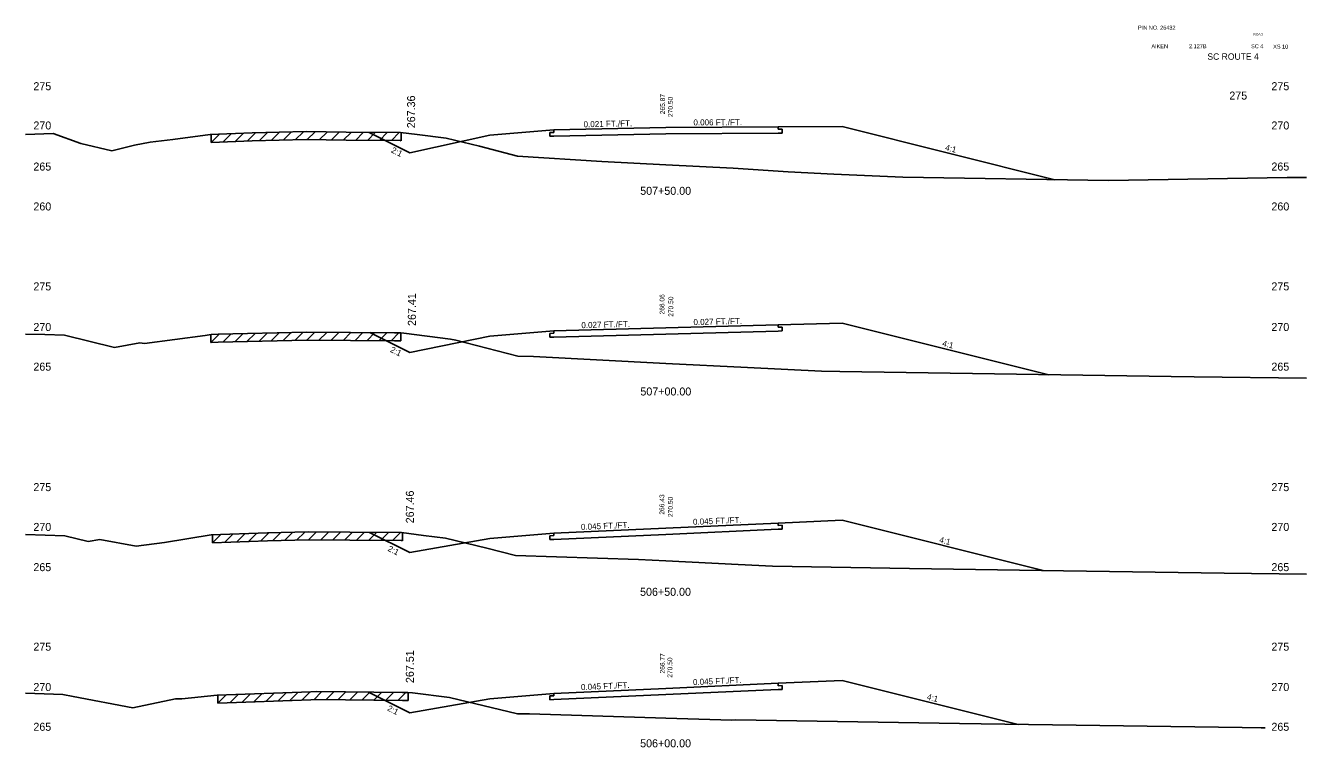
# Model space of a CAD drawing. Extents: x 883 to 1160, y 1002 to 4323.
# Drawn here: x 1000 to 1160, y 2048.1 to 2138.2 of the extents above; entities that cross this region are included whole.
import ezdxf

# ---------------------------------------------------------------- set-up
doc = ezdxf.new("R2010")
doc.units = 0
for name, color, linetype in [('Level 1', 7, 'Continuous'), ('Level 10', 7, 'Continuous'), ('Level 11', 7, 'Continuous'), ('Level 12', 7, 'Continuous'), ('Level 3', 7, 'Continuous'), ('Level 32', 7, 'Continuous'), ('Level 33', 7, 'Continuous'), ('Level 59', 7, 'Continuous'), ('Level 6', 7, 'Continuous'), ('Level 60', 7, 'Continuous'), ('Level 61', 7, 'Continuous'), ('Level 7', 7, 'Continuous')]:
    doc.layers.add(name, color=color, linetype=linetype)

msp = doc.modelspace()

# ---------------------------------------------------------------- linework, layer by layer
at = {"layer": 'Level 11'}
for p, q in [((1066, 2124.91), (1065.5, 2124.9)), ((1065.5, 2124.9), (1065.5, 2124.42)), ((1066, 2125.21), (1066, 2124.91)), ((1094, 2125.29), (1094, 2125.59)), ((1094.5, 2125.29), (1094, 2125.29)), ((1094, 2124.81), (1094.5, 2124.81)), ((1094.5, 2124.81), (1094.5, 2125.29)), ((1065.5, 2124.42), (1066, 2124.43)), ((1094, 2100.58), (1094, 2100.88)), ((1066, 2099.82), (1065.5, 2099.8)), ((1065.5, 2099.8), (1065.5, 2099.32)), ((1065.5, 2099.32), (1066, 2099.34)), ((1066, 2100.12), (1066, 2099.82)), ((1094.5, 2100.6), (1094, 2100.58)), ((1094, 2100.1), (1094.5, 2100.12)), ((1094.5, 2100.12), (1094.5, 2100.6)), ((1094, 2075.83), (1094, 2076.13)), ((1094.5, 2075.85), (1094, 2075.83)), ((1094, 2075.35), (1094.5, 2075.37)), ((1094.5, 2075.37), (1094.5, 2075.85)), ((1066, 2074.57), (1065.5, 2074.55)), ((1065.5, 2074.55), (1065.5, 2074.07)), ((1065.5, 2074.07), (1066, 2074.09)), ((1066, 2074.87), (1066, 2074.57)), ((1094, 2055.83), (1094, 2056.13)), ((1066, 2054.57), (1065.5, 2054.55)), ((1065.5, 2054.55), (1065.5, 2054.07)), ((1066, 2054.87), (1066, 2054.57)), ((1094.5, 2055.85), (1094, 2055.83)), ((1094, 2055.35), (1094.5, 2055.37)), ((1094.5, 2055.37), (1094.5, 2055.85)), ((1065.5, 2054.07), (1066, 2054.09))]:
    msp.add_line(p, q, dxfattribs=at)
at = {"layer": 'Level 12'}
for p, q in [((1094, 2124.81), (1080, 2124.72)), ((1080, 2124.72), (1066, 2124.43)), ((1080, 2099.72), (1066, 2099.34)), ((1094, 2100.1), (1080, 2099.72)), ((1094, 2075.35), (1080, 2074.72)), ((1080, 2074.72), (1066, 2074.09)), ((1080, 2054.72), (1066, 2054.09)), ((1094, 2055.35), (1080, 2054.72))]:
    msp.add_line(p, q, dxfattribs=at)
at = {"layer": 'Level 59'}
for p, q in [((1066, 2125.21), (1080, 2125.5)), ((1080, 2125.5), (1094, 2125.59)), ((1080, 2100.5), (1094, 2100.88)), ((1066, 2100.12), (1080, 2100.5)), ((1066, 2074.87), (1080, 2075.5)), ((1080, 2075.5), (1094, 2076.13)), ((1080, 2055.5), (1094, 2056.13)), ((1066, 2054.87), (1080, 2055.5))]:
    msp.add_line(p, q, dxfattribs=at)
at = {"layer": 'Level 6'}
for p, q in [((1058, 2124.54), (1066, 2125.21)), ((1094, 2125.59), (1102, 2125.64)), ((1094, 2100.88), (1102, 2101.1)), ((1058, 2099.45), (1066, 2100.12)), ((1094, 2076.13), (1102, 2076.49)), ((1058, 2074.2), (1066, 2074.87)), ((1094, 2056.13), (1102, 2056.49)), ((1058, 2054.2), (1066, 2054.87))]:
    msp.add_line(p, q, dxfattribs=at)
at = {"layer": 'Level 60'}
for p, q in [((1023.07, 2124.65), (1028.29, 2124.84)), ((1028.29, 2124.84), (1035.06, 2125)), ((1035.06, 2125), (1040.06, 2124.92)), ((1040.06, 2124.92), (1046.83, 2124.88)), ((1046.83, 2124.88), (1048.93, 2124.64)), ((1000, 2124.63), (1003.46, 2124.77)), ((1003.46, 2124.77), (1006.89, 2123.53)), ((1006.89, 2123.53), (1010.75, 2122.61)), ((1010.75, 2122.61), (1013.62, 2123.33)), ((1013.62, 2123.33), (1015.56, 2123.69)), ((1015.56, 2123.69), (1018.39, 2124.03)), ((1018.39, 2124.03), (1023.07, 2124.65)), ((1048.93, 2124.64), (1052.52, 2124.18)), ((1052.52, 2124.18), (1056.7, 2123.17)), ((1056.7, 2123.17), (1061.46, 2121.95)), ((1061.46, 2121.95), (1071.98, 2121.28)), ((1071.98, 2121.28), (1080, 2120.87)), ((1080, 2120.87), (1088.39, 2120.44)), ((1088.39, 2120.44), (1095.27, 2119.97)), ((1095.27, 2119.97), (1100.97, 2119.68)), ((1100.97, 2119.68), (1109.58, 2119.3)), ((1109.58, 2119.3), (1135.28, 2118.9)), ((1135.28, 2118.9), (1157.59, 2119.28)), ((1157.59, 2119.28), (1160, 2119.26)), ((1000, 2099.71), (1002.39, 2099.67)), ((1002.39, 2099.67), (1004.86, 2099.57)), ((1004.86, 2099.57), (1011.1, 2098.07)), ((1014.84, 2098.55), (1022.44, 2099.56)), ((1022.44, 2099.56), (1023.18, 2099.68)), ((1023.18, 2099.68), (1024.07, 2099.71)), ((1024.07, 2099.71), (1035.07, 2099.96)), ((1035.07, 2099.96), (1046.08, 2099.89)), ((1046.08, 2099.89), (1046.89, 2099.89)), ((1046.89, 2099.89), (1047.23, 2099.84)), ((1047.23, 2099.84), (1053.09, 2099.11)), ((1011.1, 2098.07), (1014.26, 2098.65)), ((1014.26, 2098.65), (1014.84, 2098.55)), ((1053.09, 2099.11), (1053.75, 2098.95)), ((1053.75, 2098.95), (1061.49, 2096.97)), ((1061.49, 2096.97), (1063.46, 2096.91)), ((1063.46, 2096.91), (1080, 2096.06)), ((1080, 2096.06), (1090.19, 2095.55)), ((1090.19, 2095.55), (1099.41, 2095.09)), ((1099.41, 2095.09), (1101.72, 2095.05)), ((1101.72, 2095.05), (1143.11, 2094.41)), ((1143.11, 2094.41), (1145.98, 2094.37)), ((1145.98, 2094.37), (1160, 2094.21)), ((1000, 2074.71), (1004.91, 2074.52)), ((1004.91, 2074.52), (1007.8, 2073.83)), ((1007.8, 2073.83), (1009.26, 2074.1)), ((1009.26, 2074.1), (1013.81, 2073.24)), ((1013.81, 2073.24), (1017.35, 2073.72)), ((1017.35, 2073.72), (1023.18, 2074.65)), ((1023.18, 2074.65), (1030.21, 2074.91)), ((1030.21, 2074.91), (1035.36, 2075.02)), ((1035.36, 2075.02), (1040.51, 2074.99)), ((1040.51, 2074.99), (1046.95, 2074.94)), ((1046.95, 2074.94), (1049.71, 2074.58)), ((1049.71, 2074.58), (1052.44, 2074.24)), ((1052.44, 2074.24), (1057.61, 2073.01)), ((1057.61, 2073.01), (1061.21, 2072.09)), ((1061.21, 2072.09), (1076.57, 2071.6)), ((1076.57, 2071.6), (1080, 2071.43)), ((1080, 2071.43), (1089.03, 2070.97)), ((1089.03, 2070.97), (1093.3, 2070.76)), ((1093.3, 2070.76), (1110.43, 2070.47)), ((1110.43, 2070.47), (1129.64, 2070.18)), ((1129.64, 2070.18), (1149.74, 2069.89)), ((1149.74, 2069.89), (1160, 2069.77)), ((1000, 2054.9), (1004.65, 2054.71)), ((1004.65, 2054.71), (1005.92, 2054.49)), ((1005.92, 2054.49), (1013.38, 2053.08)), ((1019.52, 2054.18), (1023.93, 2054.63)), ((1023.93, 2054.63), (1035.63, 2055.06)), ((1035.63, 2055.06), (1036.4, 2055.09)), ((1036.4, 2055.09), (1047.09, 2055)), ((1047.09, 2055), (1047.74, 2055)), ((1047.74, 2055), (1048.34, 2054.93)), ((1048.34, 2054.93), (1052.94, 2054.34)), ((1013.38, 2053.08), (1018.74, 2054.17)), ((1018.74, 2054.17), (1019.52, 2054.18)), ((1052.94, 2054.34), (1061.44, 2052.32)), ((1061.44, 2052.32), (1062.95, 2052.3)), ((1062.95, 2052.3), (1080, 2051.77)), ((1080, 2051.77), (1088.24, 2051.51)), ((1088.24, 2051.51), (1088.72, 2051.56)), ((1088.72, 2051.56), (1116.68, 2051.1)), ((1116.68, 2051.1), (1119.36, 2051.06)), ((1119.36, 2051.06), (1151.96, 2050.6)), ((1151.96, 2050.6), (1154.37, 2050.57)), ((1154.37, 2050.57), (1154.85, 2050.57))]:
    msp.add_line(p, q, dxfattribs=at)
at = {"layer": 'Level 61'}
for p, q in [((1027.23, 2124.8), (1026.19, 2123.77)), ((1028.72, 2124.85), (1027.69, 2123.82)), ((1030.21, 2124.89), (1029.19, 2123.86)), ((1031.71, 2124.92), (1030.69, 2123.9)), ((1033.21, 2124.96), (1032.19, 2123.93)), ((1034.71, 2124.99), (1033.69, 2123.97)), ((1036.17, 2124.98), (1035.19, 2124)), ((1037.67, 2124.95), (1036.69, 2123.97)), ((1039.17, 2124.93), (1038.19, 2123.95)), ((1040.68, 2124.91), (1039.69, 2123.92)), ((1042.18, 2124.9), (1041.19, 2123.91)), ((1043.68, 2124.89), (1042.69, 2123.9)), ((1045.18, 2124.89), (1044.19, 2123.89)), ((1046.68, 2124.88), (1045.69, 2123.88)), ((1046.91, 2123.87), (1046.91, 2124.87)), ((1024.23, 2124.69), (1023.19, 2123.65)), ((1023.19, 2124.65), (1023.19, 2123.65)), ((1023.19, 2123.65), (1028.29, 2123.84)), ((1025.73, 2124.75), (1024.69, 2123.71)), ((1028.29, 2123.84), (1035.06, 2124)), ((1035.06, 2124), (1040.06, 2123.92)), ((1040.06, 2123.92), (1046.83, 2123.88)), ((1046.83, 2123.88), (1046.91, 2123.87)), ((1024.19, 2099.71), (1023.15, 2098.67)), ((1023.15, 2099.67), (1023.15, 2098.67)), ((1025.67, 2099.75), (1024.65, 2098.72)), ((1027.17, 2099.78), (1026.15, 2098.76)), ((1028.67, 2099.81), (1027.65, 2098.79)), ((1030.17, 2099.85), (1029.15, 2098.82)), ((1031.67, 2099.88), (1030.65, 2098.86)), ((1033.17, 2099.92), (1032.15, 2098.89)), ((1034.67, 2099.95), (1033.65, 2098.93)), ((1036.14, 2099.95), (1035.15, 2098.96)), ((1037.64, 2099.94), (1036.65, 2098.95)), ((1039.14, 2099.94), (1038.15, 2098.94)), ((1040.64, 2099.93), (1039.65, 2098.93)), ((1042.14, 2099.92), (1041.15, 2098.92)), ((1043.64, 2099.91), (1042.65, 2098.91)), ((1045.14, 2099.9), (1044.15, 2098.91)), ((1046.64, 2099.89), (1045.65, 2098.9)), ((1046.89, 2098.89), (1046.89, 2099.89)), ((1023.15, 2098.67), (1023.18, 2098.68)), ((1023.18, 2098.68), (1024.07, 2098.71)), ((1024.07, 2098.71), (1035.07, 2098.96)), ((1035.07, 2098.96), (1046.08, 2098.89)), ((1046.08, 2098.89), (1046.89, 2098.89)), ((1046.89, 2098.89), (1046.89, 2098.89)), ((1024.38, 2074.69), (1023.34, 2073.65)), ((1023.34, 2074.65), (1023.34, 2073.65)), ((1023.34, 2073.65), (1030.21, 2073.91)), ((1025.88, 2074.75), (1024.84, 2073.71)), ((1027.38, 2074.8), (1026.34, 2073.76)), ((1028.88, 2074.86), (1027.84, 2073.82)), ((1030.38, 2074.91), (1029.34, 2073.87)), ((1030.21, 2073.91), (1035.36, 2074.02)), ((1031.87, 2074.94), (1030.84, 2073.92)), ((1033.37, 2074.98), (1032.34, 2073.95)), ((1034.87, 2075.01), (1033.84, 2073.99)), ((1036.34, 2075.02), (1035.34, 2074.02)), ((1035.36, 2074.02), (1040.51, 2073.99)), ((1037.84, 2075.01), (1036.84, 2074.01)), ((1039.34, 2075), (1038.34, 2074.01)), ((1040.84, 2074.99), (1039.84, 2074)), ((1040.51, 2073.99), (1046.95, 2073.94)), ((1042.33, 2074.98), (1041.34, 2073.99)), ((1043.83, 2074.96), (1042.84, 2073.97)), ((1045.33, 2074.95), (1044.34, 2073.96)), ((1046.83, 2074.94), (1045.84, 2073.95)), ((1046.95, 2073.94), (1047.09, 2073.92)), ((1047.09, 2073.92), (1047.09, 2074.92)), ((1025.04, 2054.67), (1024.01, 2053.63)), ((1024.01, 2054.63), (1024.01, 2053.63)), ((1026.54, 2054.73), (1025.51, 2053.69)), ((1028.04, 2054.78), (1027.01, 2053.75)), ((1029.55, 2054.84), (1028.51, 2053.8)), ((1031.05, 2054.89), (1030.01, 2053.86)), ((1032.55, 2054.95), (1031.51, 2053.91)), ((1034.05, 2055.01), (1033.01, 2053.97)), ((1035.55, 2055.06), (1034.51, 2054.02)), ((1037.02, 2055.09), (1036.01, 2054.08)), ((1038.5, 2055.07), (1037.51, 2054.08)), ((1040, 2055.06), (1039.01, 2054.07)), ((1041.5, 2055.05), (1040.51, 2054.06)), ((1043, 2055.03), (1042.01, 2054.04)), ((1044.5, 2055.02), (1043.51, 2054.03)), ((1046, 2055.01), (1045.01, 2054.02)), ((1047.5, 2055), (1046.51, 2054)), ((1047.81, 2053.99), (1047.81, 2054.99)), ((1024.01, 2053.63), (1035.63, 2054.06)), ((1035.63, 2054.06), (1036.4, 2054.09)), ((1036.4, 2054.09), (1047.09, 2054)), ((1047.09, 2054), (1047.74, 2054)), ((1047.74, 2054), (1047.81, 2053.99))]:
    msp.add_line(p, q, dxfattribs=at)
at = {"layer": 'Level 7'}
for p, q in [((1042.91, 2124.9), (1048, 2122.36)), ((1102, 2125.64), (1128.56, 2119)), ((1048, 2122.36), (1058, 2124.54)), ((1102, 2101.1), (1127.83, 2094.64)), ((1043, 2099.91), (1048, 2097.41)), ((1048, 2097.41), (1058, 2099.45)), ((1102, 2076.49), (1127.1, 2070.22)), ((1042.97, 2074.97), (1048, 2072.46)), ((1048, 2072.46), (1058, 2074.2)), ((1102, 2056.49), (1123.99, 2050.99)), ((1042.84, 2055.04), (1048, 2052.46)), ((1048, 2052.46), (1058, 2054.2))]:
    msp.add_line(p, q, dxfattribs=at)

# ---------------------------------------------------------------- texts
at = {"layer": 'Level 1'}
for s, height, p in [('PIN NO. 26432', 0.5, (1138.97, 2137.73)), ('AIKEN', 0.5, (1140.64, 2135.41)), (' 2.127B', 0.5, (1145.15, 2135.41)), ('SC ROUTE 4', 0.8, (1147.63, 2133.97)), ('SC 4', 0.5, (1153.09, 2135.41)), ('XS 10', 0.5, (1155.85, 2135.37)), ('507+50.00', 1, (1076.78, 2117.11)), ('507+00.00', 1, (1076.8, 2092.06)), ('506+50.00', 1, (1076.76, 2067.05)), ('506+00.00', 1, (1076.77, 2048.14))]:
    msp.add_text(s, height=height, dxfattribs=at).set_placement(p)
at = {"layer": 'Level 10'}
for s, p in [('265.87', (1079.87, 2127.17)), ('266.06', (1079.81, 2102.17)), ('266.43', (1079.79, 2077.18)), ('266.77', (1079.85, 2057.35))]:
    msp.add_text(s, height=0.6, rotation=90, dxfattribs=at).set_placement(p)
at = {"layer": 'Level 3'}
for s, height, p in [('ROAD', 0.3, (1153.38, 2137)), (' 275', 1, (1000.6, 2130.17)), (' 275', 1, (1150, 2129)), (' 275', 1, (1155.26, 2130.17)), (' 270', 1, (1000.6, 2125.27)), (' 270', 1, (1155.26, 2125.27)), (' 265', 1, (1000.6, 2120.14)), (' 265', 1, (1155.26, 2120.14)), (' 260', 1, (1000.6, 2115.16)), (' 260', 1, (1155.26, 2115.16)), (' 275', 1, (1000.6, 2105.18)), (' 275', 1, (1155.26, 2105.18)), (' 270', 1, (1000.6, 2100.11)), (' 270', 1, (1155.26, 2100.11)), (' 265', 1, (1000.6, 2095.16)), (' 265', 1, (1155.26, 2095.16)), (' 275', 1, (1000.6, 2080.12)), (' 275', 1, (1155.26, 2080.12)), (' 270', 1, (1000.6, 2075.15)), (' 270', 1, (1155.26, 2075.15)), (' 265', 1, (1000.6, 2070.13)), (' 265', 1, (1155.26, 2070.13)), (' 275', 1, (1000.6, 2060.2)), (' 275', 1, (1155.26, 2060.2)), (' 270', 1, (1000.6, 2055.16)), (' 270', 1, (1155.26, 2055.16)), (' 265', 1, (1000.6, 2050.2)), (' 265', 1, (1155.26, 2050.2))]:
    msp.add_text(s, height=height, dxfattribs=at).set_placement(p)
at = {"layer": 'Level 32'}
for s, rotation, p in [('0.021 FT./FT.', 1.1916, (1069.71, 2125.54)), ('0.006 FT./FT.', 0.3723, (1083.43, 2125.77)), ('4:1', 345.9638, (1114.82, 2122.69)), ('2:1', 333.435, (1045.59, 2122.45)), ('0.027 FT./FT.', 1.5631, (1069.44, 2100.46)), ('0.027 FT./FT.', 1.565, (1083.44, 2100.84)), ('2:1', 333.435, (1045.48, 2097.54)), ('4:1', 345.9638, (1114.46, 2098.24)), ('0.045 FT./FT.', 2.5766, (1083.39, 2075.9)), ('0.045 FT./FT.', 2.5766, (1069.39, 2075.27)), ('4:1', 345.9638, (1114.09, 2073.72)), ('2:1', 333.435, (1045.17, 2072.7)), ('0.045 FT./FT.', 2.5766, (1069.39, 2055.27)), ('0.045 FT./FT.', 2.5766, (1083.39, 2055.9)), ('4:1', 345.9638, (1112.54, 2054.11)), ('2:1', 333.435, (1045.11, 2052.77))]:
    msp.add_text(s, height=0.75, rotation=rotation, dxfattribs=at).set_placement(p)
at = {"layer": 'Level 33'}
for s, p in [('267.36', (1048.66, 2125.42)), ('267.41', (1048.75, 2100.74)), ('267.46', (1048.5, 2076.1)), ('267.51', (1048.5, 2056.16))]:
    msp.add_text(s, height=1, rotation=90, dxfattribs=at).set_placement(p)
at = {"layer": 'Level 59'}
for p in [(1080.85, 2126.59), (1080.91, 2101.65), (1080.85, 2076.65), (1080.79, 2056.59)]:
    msp.add_text(' 270.50', height=0.6, rotation=90, dxfattribs=at).set_placement(p)

doc.saveas('drawing.dxf')
